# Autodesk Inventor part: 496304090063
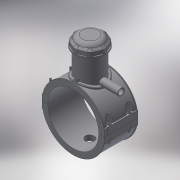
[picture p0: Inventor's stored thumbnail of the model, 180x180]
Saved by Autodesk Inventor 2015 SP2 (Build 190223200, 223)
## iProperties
Created: 2017-07
Part Number: 496304090063
Material: Generic
Description: PLASSON TAPPING SADDLE 90x63
Document SubType Name: Modeling
Designer: KIM
Mass: 888.833 g
Surface Area: 2125.84 cm^2
Volume: 888.833 cm^3
Density: 1 g/cm^3
Appearance: Default
Author: KIM
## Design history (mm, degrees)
derived "496304.ipt"
feature "Solid1::496304.ipt"
feature "Solid2::496304.ipt"
feature "Solid4::496304.ipt"
feature "Solid5::496304.ipt"
tag "TaggingFeature1"
body "Solid1"
body "Solid2"
other parameters: "d2" = 126, "d3" = 22.5, "d4" = 118, "d5" = 0, "d6" = 0.1, "d8" = 0, "d19" = 6, "d20" = 6, "d21" = 70.8, "d23" = 0, "d24" = 35.4, "d26" = 0, "d29" = 3, "d31" = 6, "d32" = 0, "d33" = 0, "d34" = 0.6, "d40" = 58.032, "d41" = 74.7, "d43" = 0, "d45" = 0, "d47" = 126.6, "d70" = 15, "d72" = 0, "d73" = 6, "d75" = 5, "d76" = 0, "d77" = 4.5, "d78" = 75, "d79" = 15, "d80" = 47.2, "d82" = 5 deg, "d84" = 4, "d85" = 14, "d86" = 0, "d87" = 3, "d88" = 0, "d89" = 1, "d90" = 1, "d91" = 94.4, "d92" = 0, "d93" = 0.5, "d94" = 47.36842, "d96" = 113.832, "d97" = 2.36, "d98" = 0, "d102" = 0.9, "d120" = 140 deg, "d121" = 24.228, "d122" = 20 deg, "d123" = 223.2, "d124" = 66.96, "d126" = 0, "d143" = 92.7, "d145" = 16.61538, "d149" = 1.35, "d150" = 18.27692, "d153" = 118, "d154" = 0, "d156" = 55.8, "d157" = 160 deg, "d159" = 4.32, "d161" = 1.35, "d162" = 70.8, "d163" = 0, "d164" = 45, "d167" = 9, "d168" = 54.43902, "d170" = 3.375, "d172" = 0, "d173" = 1, "d175" = 45, "d176" = 20 deg, "d177" = 6.3, "d178" = 21.6, "d180" = 0, "d183" = 8.64, "d184" = 5.04, "d185" = 38.35, "d186" = 38.35, "d187" = 55.8, "d188" = 6.48, "d189" = 6.3, "d190" = 0, "d191" = 83.7, "d193" = 6.3, "d194" = 4.13, "d195" = 90 deg, "d197" = 0, "d199" = 0, "d200" = 10.8, "d202" = 0, "d203" = 177, "d204" = 70.965, "d205" = 52.29, "d206" = 63.495, "d207" = 132.75, "d208" = 138.06, "d209" = 164.61, "d210" = 64.242, "d211" = 74.7, "d212" = 59.76, "d213" = 29.25, "d216" = 0, "d217" = 9, "d218" = 9, "d219" = 1.8, "d224" = 0, "d230" = 5.4, "d233" = 6, "d236" = 63, "d237" = 35.4, "d238" = 6.02433, "d240" = 35.4, "d241" = 35.4, "d242" = 35.4, "d243" = 6, "d244" = 35.4, "d245" = 35.4, "d246" = 35.4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
